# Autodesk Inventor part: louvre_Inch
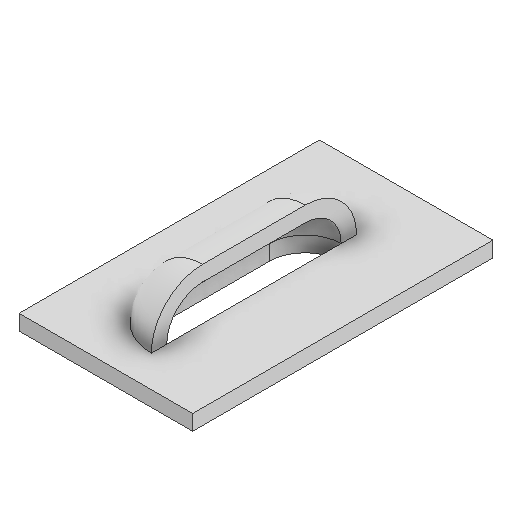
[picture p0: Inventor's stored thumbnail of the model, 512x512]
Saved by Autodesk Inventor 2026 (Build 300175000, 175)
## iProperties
Created: 2025-03
Part Number: louvre_Inch
Material: Generic
Document SubType Name: Sheet Metal
Designer: itools
Density: 1 g/cm^3
Sheet Metal Rule: Default
Appearance: Default
MinimumRemnant: 3.000 mm
Author: itools
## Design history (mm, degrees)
node "Face1"
  sketch "Sketch1"
    geometry: L1 (11.817, 24.592)-(-5.379, 24.592); L2 (-5.379, 24.592)-(-5.379, -5.155); L3 (-5.379, -5.155)-(11.817, -5.155); L4 (11.817, -5.155)-(11.817, 24.592)
    constraints: 8 end point, 2 parallel, 1 horizontal, 1 perpendicular
sketch "Sketch2"
  geometry: L1 (-1.927, -1.454)-(-1.927, -1.454); L2 (-6.927, -6.454)-(-6.927, -16.454); L3 (-1.927, -21.454)-(-1.927, -21.454); L4 (-1.927, -21.454)-(-1.927, -1.454); L5 (-1.927, -1.454)-(-6.927, -21.454); L6 (-6.927, -1.454)-(-1.927, -21.454); A1 r 5 centre (-1.927, -16.454) between (-6.927, -16.454) and (-1.927, -21.454); A2 r 5 centre (-1.927, -6.454) between (-1.927, -1.454) and (-6.927, -6.454); 3 further points
  constraints: 12 end point, 4 point on circle, 4 point on line, 4 tangent, 2 centre point, 2 midpoint, 2 parallel, 1 equal radius, 1 horizontal, 1 perpendicular
  dimensions: "d1" = 5 radius of A1 (= Width); "Width" = 5 distance between parallel lines of L4 L2; "Length" = 20 distance of L3.end L1.start
revolve "Revolution1" sketch "Sketch2" stored, may be unused: angle "Angle" = 90 deg
sketch "Sketch3"
  geometry: L1 (15, 5)-(5, 5) reference; L2 (5, 3.5)-(15, 3.5); L3 (1.5, 0)-(18.5, 0); L4 (20, 0)-(0, 0) reference; A1 r 5 centre (5, 0) between (5, 5) and (0, 0) reference; A2 r 5 centre (15, 0) between (20, 0) and (15, 5) reference; A3 r 3.5 centre (5, 0) between (5, 3.5) and (1.5, 0); A4 r 3.5 centre (15, 0) between (18.5, 0) and (15, 3.5); 1 further point
  constraints: 4 end point, 4 point on circle, 2 centre point, 1 collinear, 2 other
  dimensions: "d5" = 1.5 distance between parallel lines of L1 L2 (= Thickness)
revolve "Revolution2" sketch "Sketch3" stored, may be unused: angle "d6" = 90 deg (= Angle)
sketch "Sketch4"
  geometry: L1 (-5.427, -16.454)-(-5.427, -6.454) reference; L2 (-1.927, -1.454)-(-1.927, -2.954) reference; L3 (-1.927, -2.954)-(-1.927, -19.954); A1 r 3.5 centre (-1.927, -16.454) between (-5.427, -16.454) and (-1.927, -19.954) reference; A2 r 3.5 centre (-1.927, -6.454) between (-1.927, -2.954) and (-5.427, -6.454) reference; 1 further point
  constraints: 2 end point, 1 collinear
extrude "Extrusion1" cut sketch "Sketch4" distance "d7" = 1.5 (= Thickness); taper "d8" = 0 deg
body "Solid1"
face "Plate1" dims "d0" = 1.5 (= Thickness)
other parameters: "Thickness" = 1.5, "BendRadius" = 1.5 (= Thickness), "BendReliefWidth" = 1.5 (= Thickness), "BendReliefDepth" = 0.75 (= 0.5 x Thickness), "CornerReliefSize" = 6 (= 4 x Thickness), "SeamGap" = 0.00508, "MinimumRemnant" = 3 (= 2 x Thickness), "TransitionRadius" = 1.5 (= BendRadius), "JacobiRadiusSize" = 1.5 (= BendRadius), "GapSize" = 1.5 (= Thickness)
